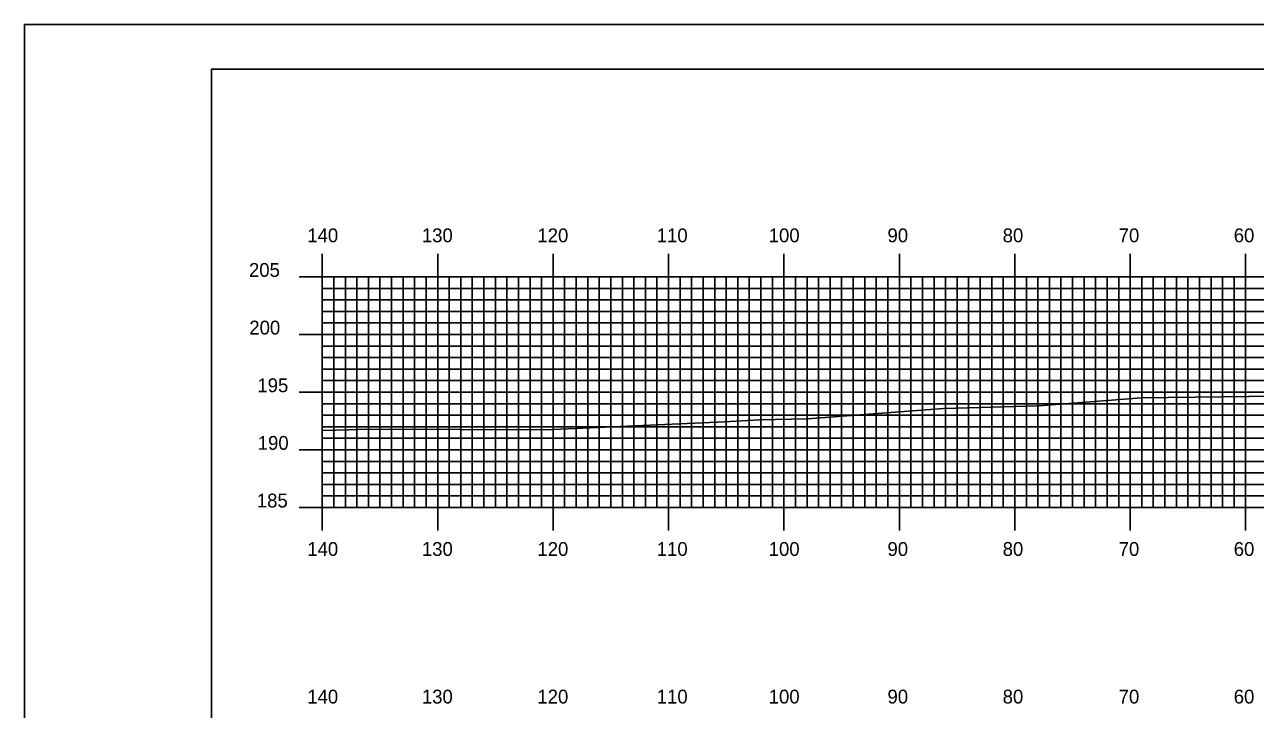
# Model space of a CAD drawing. Extents: x 1814522 to 1814865, y 442591 to 442811.
# Drawn here: x 1814521.7 to 1814628.4, y 442751.2 to 442810.5 of the extents above; entities that cross this region are included whole.
import ezdxf

# ---------------------------------------------------------------- set-up
doc = ezdxf.new("R2010")
doc.units = 0
for name, color, linetype in [('BORDER', 7, 'Continuous'), ('H_V ANNOTATION', 7, 'Continuous'), ('MAJOR', 7, 'Continuous'), ('MINOR', 7, 'Continuous'), ('PLOT BOUNDARY', 7, 'Continuous'), ('S_Roadway_Centerline', 7, 'Continuous')]:
    doc.layers.add(name, color=color, linetype=linetype)

msp = doc.modelspace()

# ---------------------------------------------------------------- linework, layer by layer
at = {"layer": 'BORDER'}
msp.add_lwpolyline([(1814537.91, 442596.67), (1814857.91, 442596.67), (1814857.91, 442806.67), (1814537.91, 442806.67)], close=True, dxfattribs=at)
at = {"layer": 'MAJOR'}
for p, q in [((1814547.51, 442790.67), (1814547.51, 442788.67)), ((1814557.51, 442790.67), (1814557.51, 442788.67)), ((1814567.51, 442790.67), (1814567.51, 442788.67)), ((1814577.51, 442790.67), (1814577.51, 442788.67)), ((1814587.51, 442790.67), (1814587.51, 442788.67)), ((1814597.51, 442790.67), (1814597.51, 442788.67)), ((1814607.51, 442790.67), (1814607.51, 442788.67)), ((1814617.51, 442790.67), (1814617.51, 442788.67)), ((1814627.51, 442790.67), (1814627.51, 442788.67)), ((1814545.5, 442788.67), (1814547.51, 442788.67)), ((1814547.51, 442788.67), (1814827.51, 442788.67)), ((1814547.51, 442768.67), (1814547.51, 442788.67)), ((1814547.51, 442768.67), (1814547.51, 442788.67)), ((1814547.51, 442788.67), (1814827.51, 442788.67)), ((1814557.51, 442768.67), (1814557.51, 442788.67)), ((1814567.51, 442768.67), (1814567.51, 442788.67)), ((1814577.51, 442768.67), (1814577.51, 442788.67)), ((1814587.51, 442768.67), (1814587.51, 442788.67)), ((1814597.51, 442768.67), (1814597.51, 442788.67)), ((1814607.51, 442768.67), (1814607.51, 442788.67)), ((1814617.51, 442768.67), (1814617.51, 442788.67)), ((1814627.51, 442768.67), (1814627.51, 442788.67)), ((1814545.5, 442783.67), (1814547.51, 442783.67)), ((1814547.51, 442783.67), (1814827.51, 442783.67)), ((1814545.5, 442778.67), (1814547.51, 442778.67)), ((1814547.51, 442778.67), (1814827.51, 442778.67)), ((1814545.5, 442773.67), (1814547.51, 442773.67)), ((1814547.51, 442773.67), (1814827.51, 442773.67)), ((1814545.5, 442768.67), (1814547.51, 442768.67)), ((1814547.51, 442768.67), (1814827.51, 442768.67)), ((1814547.51, 442768.67), (1814827.51, 442768.67)), ((1814547.51, 442766.66), (1814547.51, 442768.67)), ((1814557.51, 442766.66), (1814557.51, 442768.67)), ((1814567.51, 442766.66), (1814567.51, 442768.67)), ((1814577.51, 442766.66), (1814577.51, 442768.67)), ((1814587.51, 442766.66), (1814587.51, 442768.67)), ((1814597.51, 442766.66), (1814597.51, 442768.67)), ((1814607.51, 442766.66), (1814607.51, 442768.67)), ((1814617.51, 442766.66), (1814617.51, 442768.67)), ((1814627.51, 442766.66), (1814627.51, 442768.67))]:
    msp.add_line(p, q, dxfattribs=at)
at = {"layer": 'MINOR'}
for p, q in [((1814548.51, 442768.67), (1814548.51, 442788.67)), ((1814549.51, 442768.67), (1814549.51, 442788.67)), ((1814550.51, 442768.67), (1814550.51, 442788.67)), ((1814551.51, 442768.67), (1814551.51, 442788.67)), ((1814552.51, 442768.67), (1814552.51, 442788.67)), ((1814553.51, 442768.67), (1814553.51, 442788.67)), ((1814554.51, 442768.67), (1814554.51, 442788.67)), ((1814555.51, 442768.67), (1814555.51, 442788.67)), ((1814556.51, 442768.67), (1814556.51, 442788.67)), ((1814558.51, 442768.67), (1814558.51, 442788.67)), ((1814559.51, 442768.67), (1814559.51, 442788.67)), ((1814560.51, 442768.67), (1814560.51, 442788.67)), ((1814561.51, 442768.67), (1814561.51, 442788.67)), ((1814562.51, 442768.67), (1814562.51, 442788.67)), ((1814563.51, 442768.67), (1814563.51, 442788.67)), ((1814564.51, 442768.67), (1814564.51, 442788.67)), ((1814565.51, 442768.67), (1814565.51, 442788.67)), ((1814566.51, 442768.67), (1814566.51, 442788.67)), ((1814568.51, 442768.67), (1814568.51, 442788.67)), ((1814569.51, 442768.67), (1814569.51, 442788.67)), ((1814570.51, 442768.67), (1814570.51, 442788.67)), ((1814571.51, 442768.67), (1814571.51, 442788.67)), ((1814572.51, 442768.67), (1814572.51, 442788.67)), ((1814573.51, 442768.67), (1814573.51, 442788.67)), ((1814574.51, 442768.67), (1814574.51, 442788.67)), ((1814575.51, 442768.67), (1814575.51, 442788.67)), ((1814576.51, 442768.67), (1814576.51, 442788.67)), ((1814578.51, 442768.67), (1814578.51, 442788.67)), ((1814579.51, 442768.67), (1814579.51, 442788.67)), ((1814580.51, 442768.67), (1814580.51, 442788.67)), ((1814581.51, 442768.67), (1814581.51, 442788.67)), ((1814582.51, 442768.67), (1814582.51, 442788.67)), ((1814583.51, 442768.67), (1814583.51, 442788.67)), ((1814584.51, 442768.67), (1814584.51, 442788.67)), ((1814585.51, 442768.67), (1814585.51, 442788.67)), ((1814586.51, 442768.67), (1814586.51, 442788.67)), ((1814588.51, 442768.67), (1814588.51, 442788.67)), ((1814589.51, 442768.67), (1814589.51, 442788.67)), ((1814590.51, 442768.67), (1814590.51, 442788.67)), ((1814591.51, 442768.67), (1814591.51, 442788.67)), ((1814592.51, 442768.67), (1814592.51, 442788.67)), ((1814593.51, 442768.67), (1814593.51, 442788.67)), ((1814594.51, 442768.67), (1814594.51, 442788.67)), ((1814595.51, 442768.67), (1814595.51, 442788.67)), ((1814596.51, 442768.67), (1814596.51, 442788.67)), ((1814598.51, 442768.67), (1814598.51, 442788.67)), ((1814599.51, 442768.67), (1814599.51, 442788.67)), ((1814600.51, 442768.67), (1814600.51, 442788.67)), ((1814601.51, 442768.67), (1814601.51, 442788.67)), ((1814602.51, 442768.67), (1814602.51, 442788.67)), ((1814603.51, 442768.67), (1814603.51, 442788.67)), ((1814604.51, 442768.67), (1814604.51, 442788.67)), ((1814605.51, 442768.67), (1814605.51, 442788.67)), ((1814606.51, 442768.67), (1814606.51, 442788.67)), ((1814608.51, 442768.67), (1814608.51, 442788.67)), ((1814609.51, 442768.67), (1814609.51, 442788.67)), ((1814610.51, 442768.67), (1814610.51, 442788.67)), ((1814611.51, 442768.67), (1814611.51, 442788.67)), ((1814612.51, 442768.67), (1814612.51, 442788.67)), ((1814613.51, 442768.67), (1814613.51, 442788.67)), ((1814614.51, 442768.67), (1814614.51, 442788.67)), ((1814615.51, 442768.67), (1814615.51, 442788.67)), ((1814616.51, 442768.67), (1814616.51, 442788.67)), ((1814618.51, 442768.67), (1814618.51, 442788.67)), ((1814619.51, 442768.67), (1814619.51, 442788.67)), ((1814620.51, 442768.67), (1814620.51, 442788.67)), ((1814621.51, 442768.67), (1814621.51, 442788.67)), ((1814622.51, 442768.67), (1814622.51, 442788.67)), ((1814623.51, 442768.67), (1814623.51, 442788.67)), ((1814624.51, 442768.67), (1814624.51, 442788.67)), ((1814625.51, 442768.67), (1814625.51, 442788.67)), ((1814626.51, 442768.67), (1814626.51, 442788.67)), ((1814547.51, 442787.67), (1814827.51, 442787.67)), ((1814547.51, 442787.67), (1814549.51, 442787.67)), ((1814547.51, 442786.67), (1814827.51, 442786.67)), ((1814547.51, 442786.67), (1814549.51, 442786.67)), ((1814547.51, 442785.67), (1814827.51, 442785.67)), ((1814547.51, 442785.67), (1814549.51, 442785.67)), ((1814547.51, 442784.67), (1814827.51, 442784.67)), ((1814547.51, 442784.67), (1814549.51, 442784.67)), ((1814547.51, 442782.67), (1814827.51, 442782.67)), ((1814547.51, 442782.67), (1814549.51, 442782.67)), ((1814547.51, 442781.67), (1814827.51, 442781.67)), ((1814547.51, 442781.67), (1814549.51, 442781.67)), ((1814547.51, 442780.67), (1814827.51, 442780.67)), ((1814547.51, 442780.67), (1814549.51, 442780.67)), ((1814547.51, 442779.67), (1814827.51, 442779.67)), ((1814547.51, 442779.67), (1814549.51, 442779.67)), ((1814547.51, 442777.67), (1814827.51, 442777.67)), ((1814547.51, 442777.67), (1814549.51, 442777.67)), ((1814547.51, 442776.67), (1814827.51, 442776.67)), ((1814547.51, 442776.67), (1814549.51, 442776.67)), ((1814547.51, 442775.67), (1814827.51, 442775.67)), ((1814547.51, 442775.67), (1814549.51, 442775.67)), ((1814547.51, 442774.67), (1814827.51, 442774.67)), ((1814547.51, 442774.67), (1814549.51, 442774.67)), ((1814547.51, 442772.67), (1814827.51, 442772.67)), ((1814547.51, 442772.67), (1814549.51, 442772.67)), ((1814547.51, 442771.67), (1814827.51, 442771.67)), ((1814547.51, 442771.67), (1814549.51, 442771.67)), ((1814547.51, 442770.67), (1814827.51, 442770.67)), ((1814547.51, 442770.67), (1814549.51, 442770.67)), ((1814547.51, 442769.67), (1814827.51, 442769.67)), ((1814547.51, 442769.67), (1814549.51, 442769.67))]:
    msp.add_line(p, q, dxfattribs=at)
at = {"layer": 'PLOT BOUNDARY'}
msp.add_lwpolyline([(1814521.72, 442590.55), (1814861.72, 442590.55), (1814861.72, 442810.55), (1814521.72, 442810.55)], close=True, dxfattribs=at)
at = {"layer": 'S_Roadway_Centerline'}
msp.add_lwpolyline([(1814547.51, 442775.34), (1814549.8, 442775.41), (1814551.37, 442775.45), (1814559.5, 442775.44), (1814566.92, 442775.41), (1814568.14, 442775.47), (1814582.37, 442776.09), (1814585.38, 442776.26), (1814589.54, 442776.36), (1814601.33, 442777.25), (1814609.58, 442777.48), (1814618.49, 442778.17), (1814630.09, 442778.31)], dxfattribs=at)

# ---------------------------------------------------------------- texts
at = {"layer": 'H_V ANNOTATION'}
for s, p in [('140', (1814546.21, 442791.67)), ('130', (1814556.14, 442791.67)), ('120', (1814566.15, 442791.67)), ('110', (1814576.49, 442791.67)), ('100', (1814586.19, 442791.67)), ('90', (1814596.48, 442791.67)), ('80', (1814606.46, 442791.67)), ('70', (1814616.51, 442791.67)), ('60', (1814626.48, 442791.67)), ('205', (1814541.16, 442788.67)), ('200', (1814541.19, 442783.67)), ('195', (1814541.89, 442778.67)), ('190', (1814541.92, 442773.67)), ('185', (1814541.84, 442768.67)), ('140', (1814546.21, 442764.47)), ('130', (1814556.14, 442764.47)), ('120', (1814566.15, 442764.47)), ('110', (1814576.49, 442764.47)), ('100', (1814586.19, 442764.47)), ('90', (1814596.48, 442764.47)), ('80', (1814606.46, 442764.47)), ('70', (1814616.51, 442764.47)), ('60', (1814626.48, 442764.47)), ('140', (1814546.21, 442751.67)), ('130', (1814556.14, 442751.67)), ('120', (1814566.15, 442751.67)), ('110', (1814576.49, 442751.67)), ('100', (1814586.19, 442751.67)), ('90', (1814596.48, 442751.67)), ('80', (1814606.46, 442751.67)), ('70', (1814616.51, 442751.67)), ('60', (1814626.48, 442751.67))]:
    msp.add_text(s, height=1.2, dxfattribs=at).set_placement(p)
at = {"layer": 'MAJOR'}
msp.add_text('-', height=0.012, dxfattribs=at).set_placement((1814547.5, 442768.67))

doc.saveas('drawing.dxf')
